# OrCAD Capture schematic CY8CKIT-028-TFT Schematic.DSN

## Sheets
1 01. Title Page: title: CY8CKIT-028-TFT TFT Display Shield; rev: 04; note: 630-60377-01
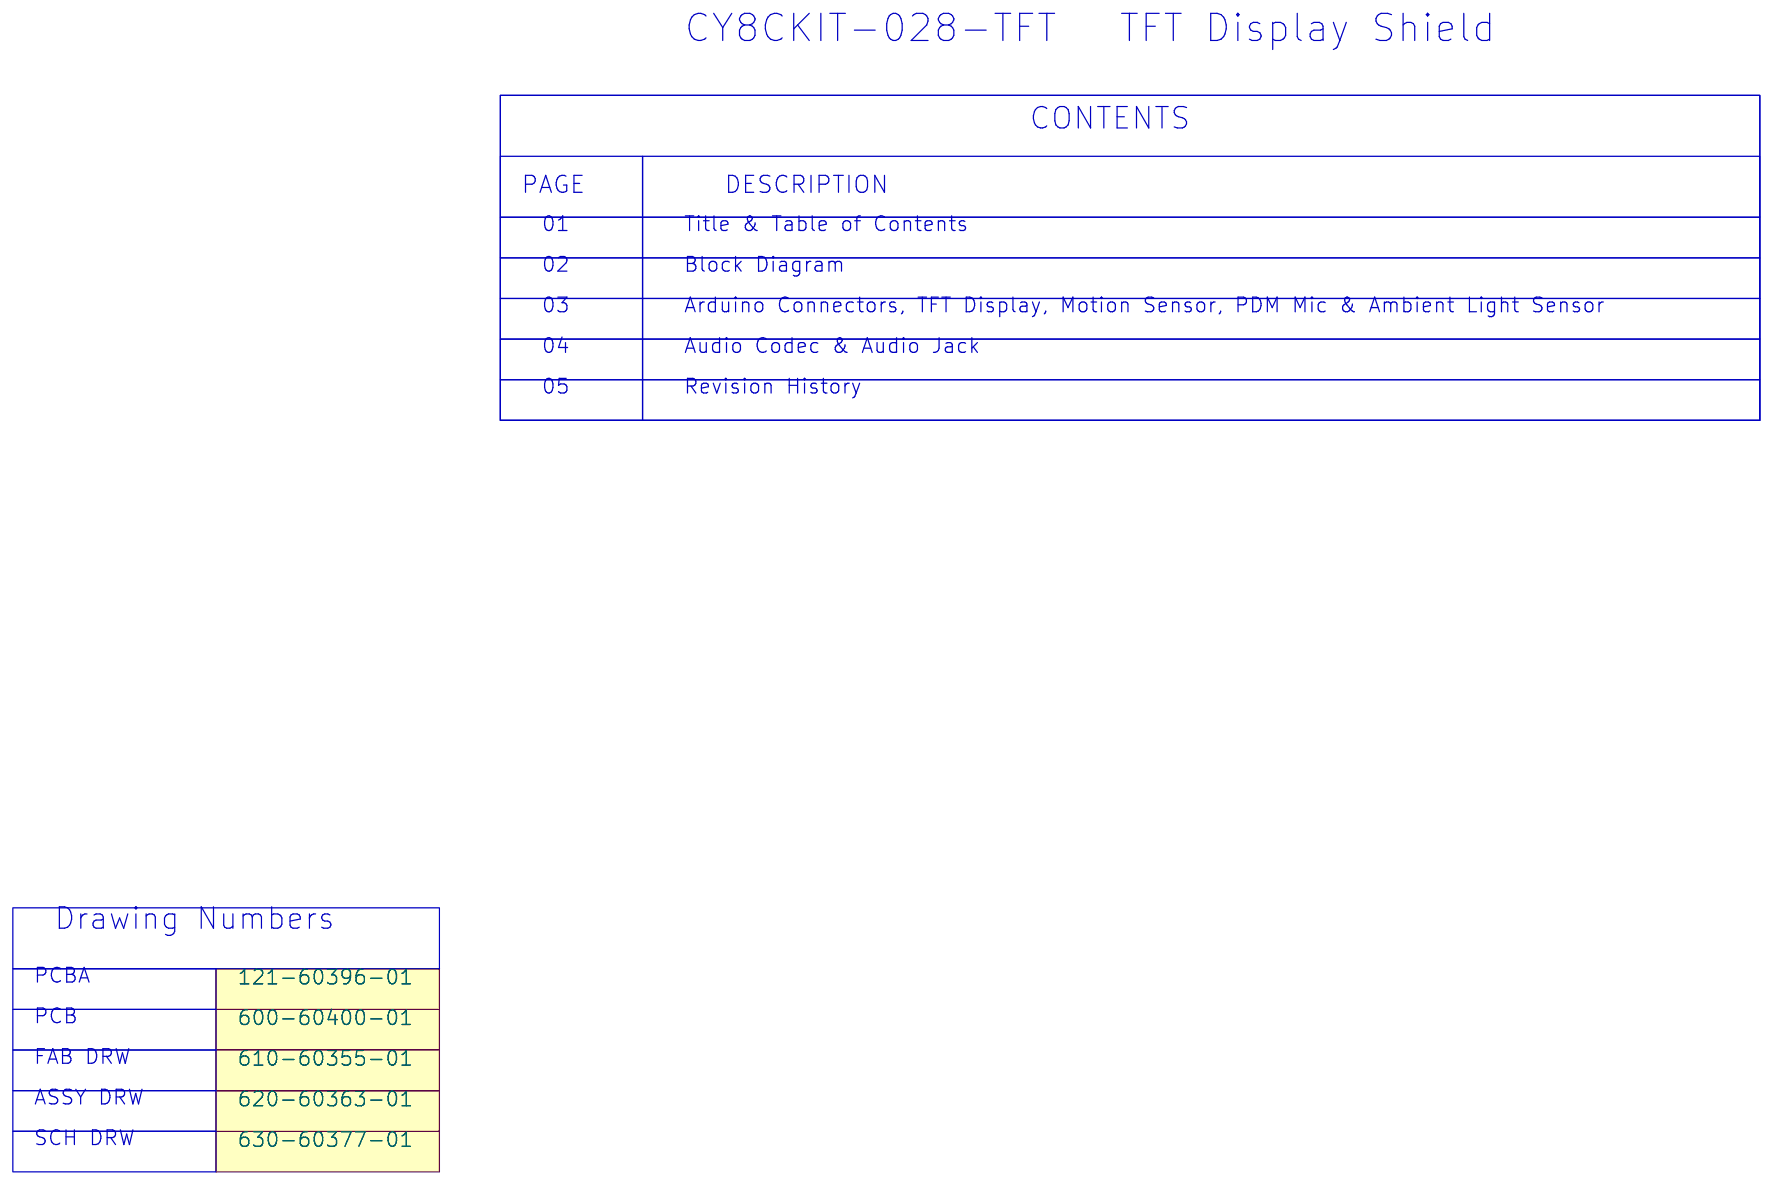
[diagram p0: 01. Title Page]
2 02. Block Diagram
3 03. Arduino,TFT, PDM, IMU & ALS: size A4
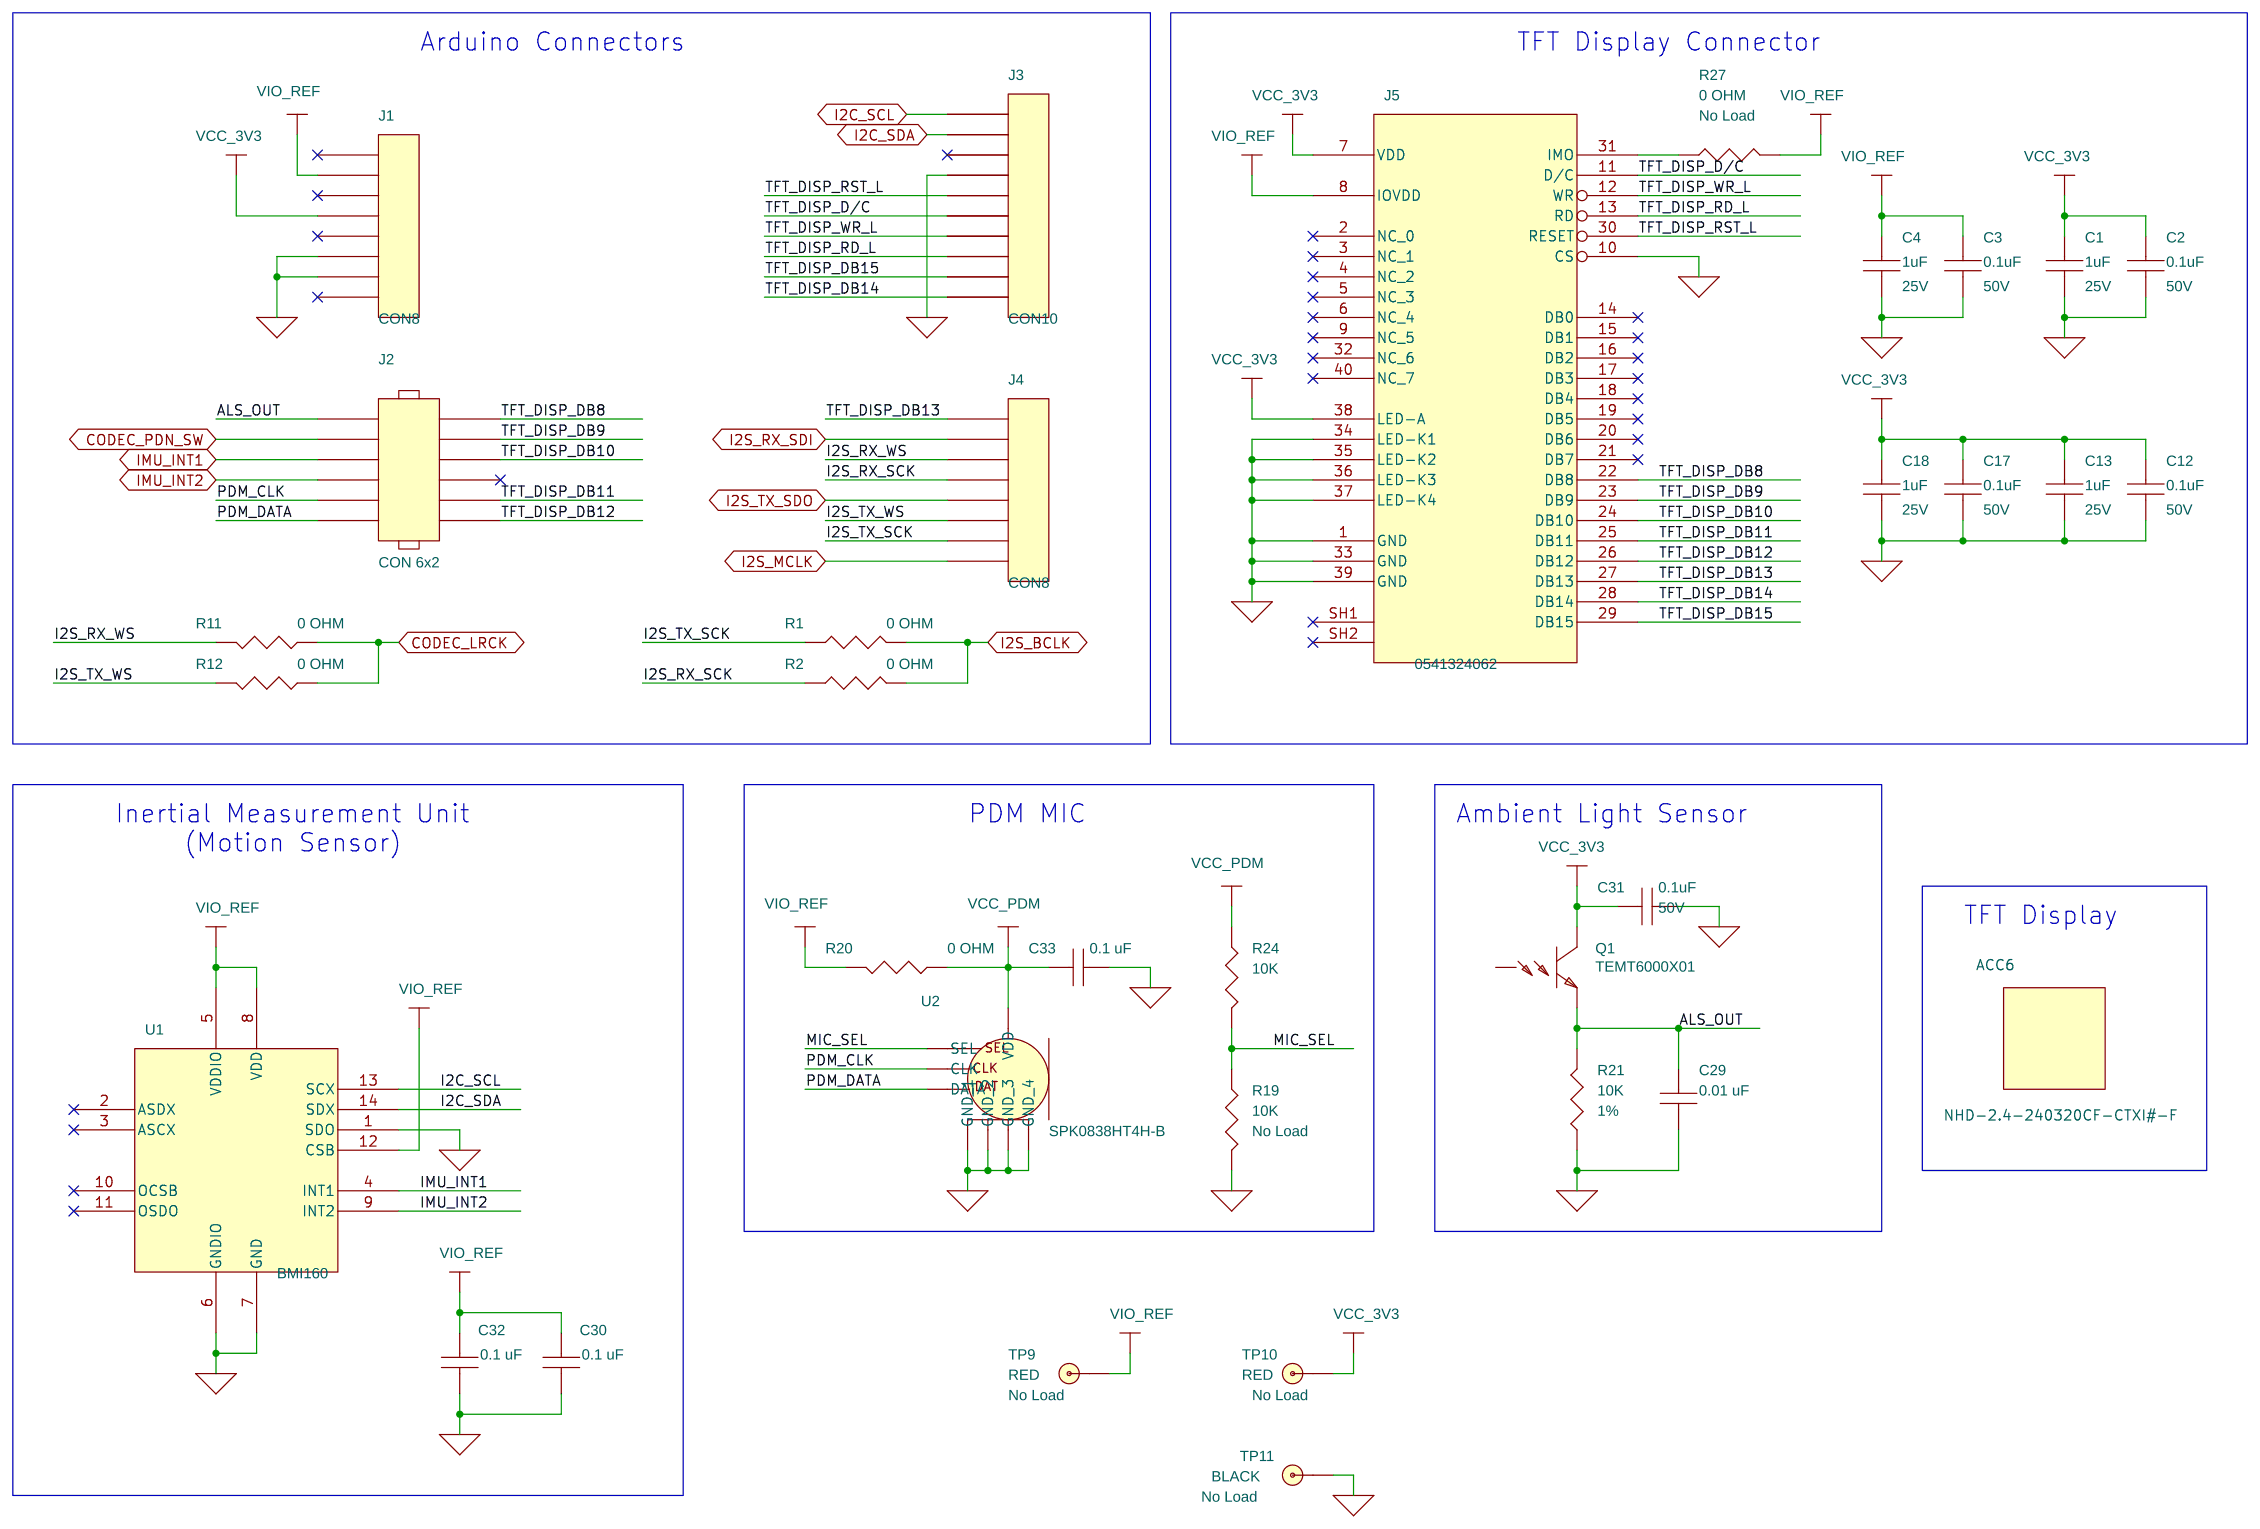
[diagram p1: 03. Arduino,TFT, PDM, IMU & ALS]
4 04. Audio Codec: size A4
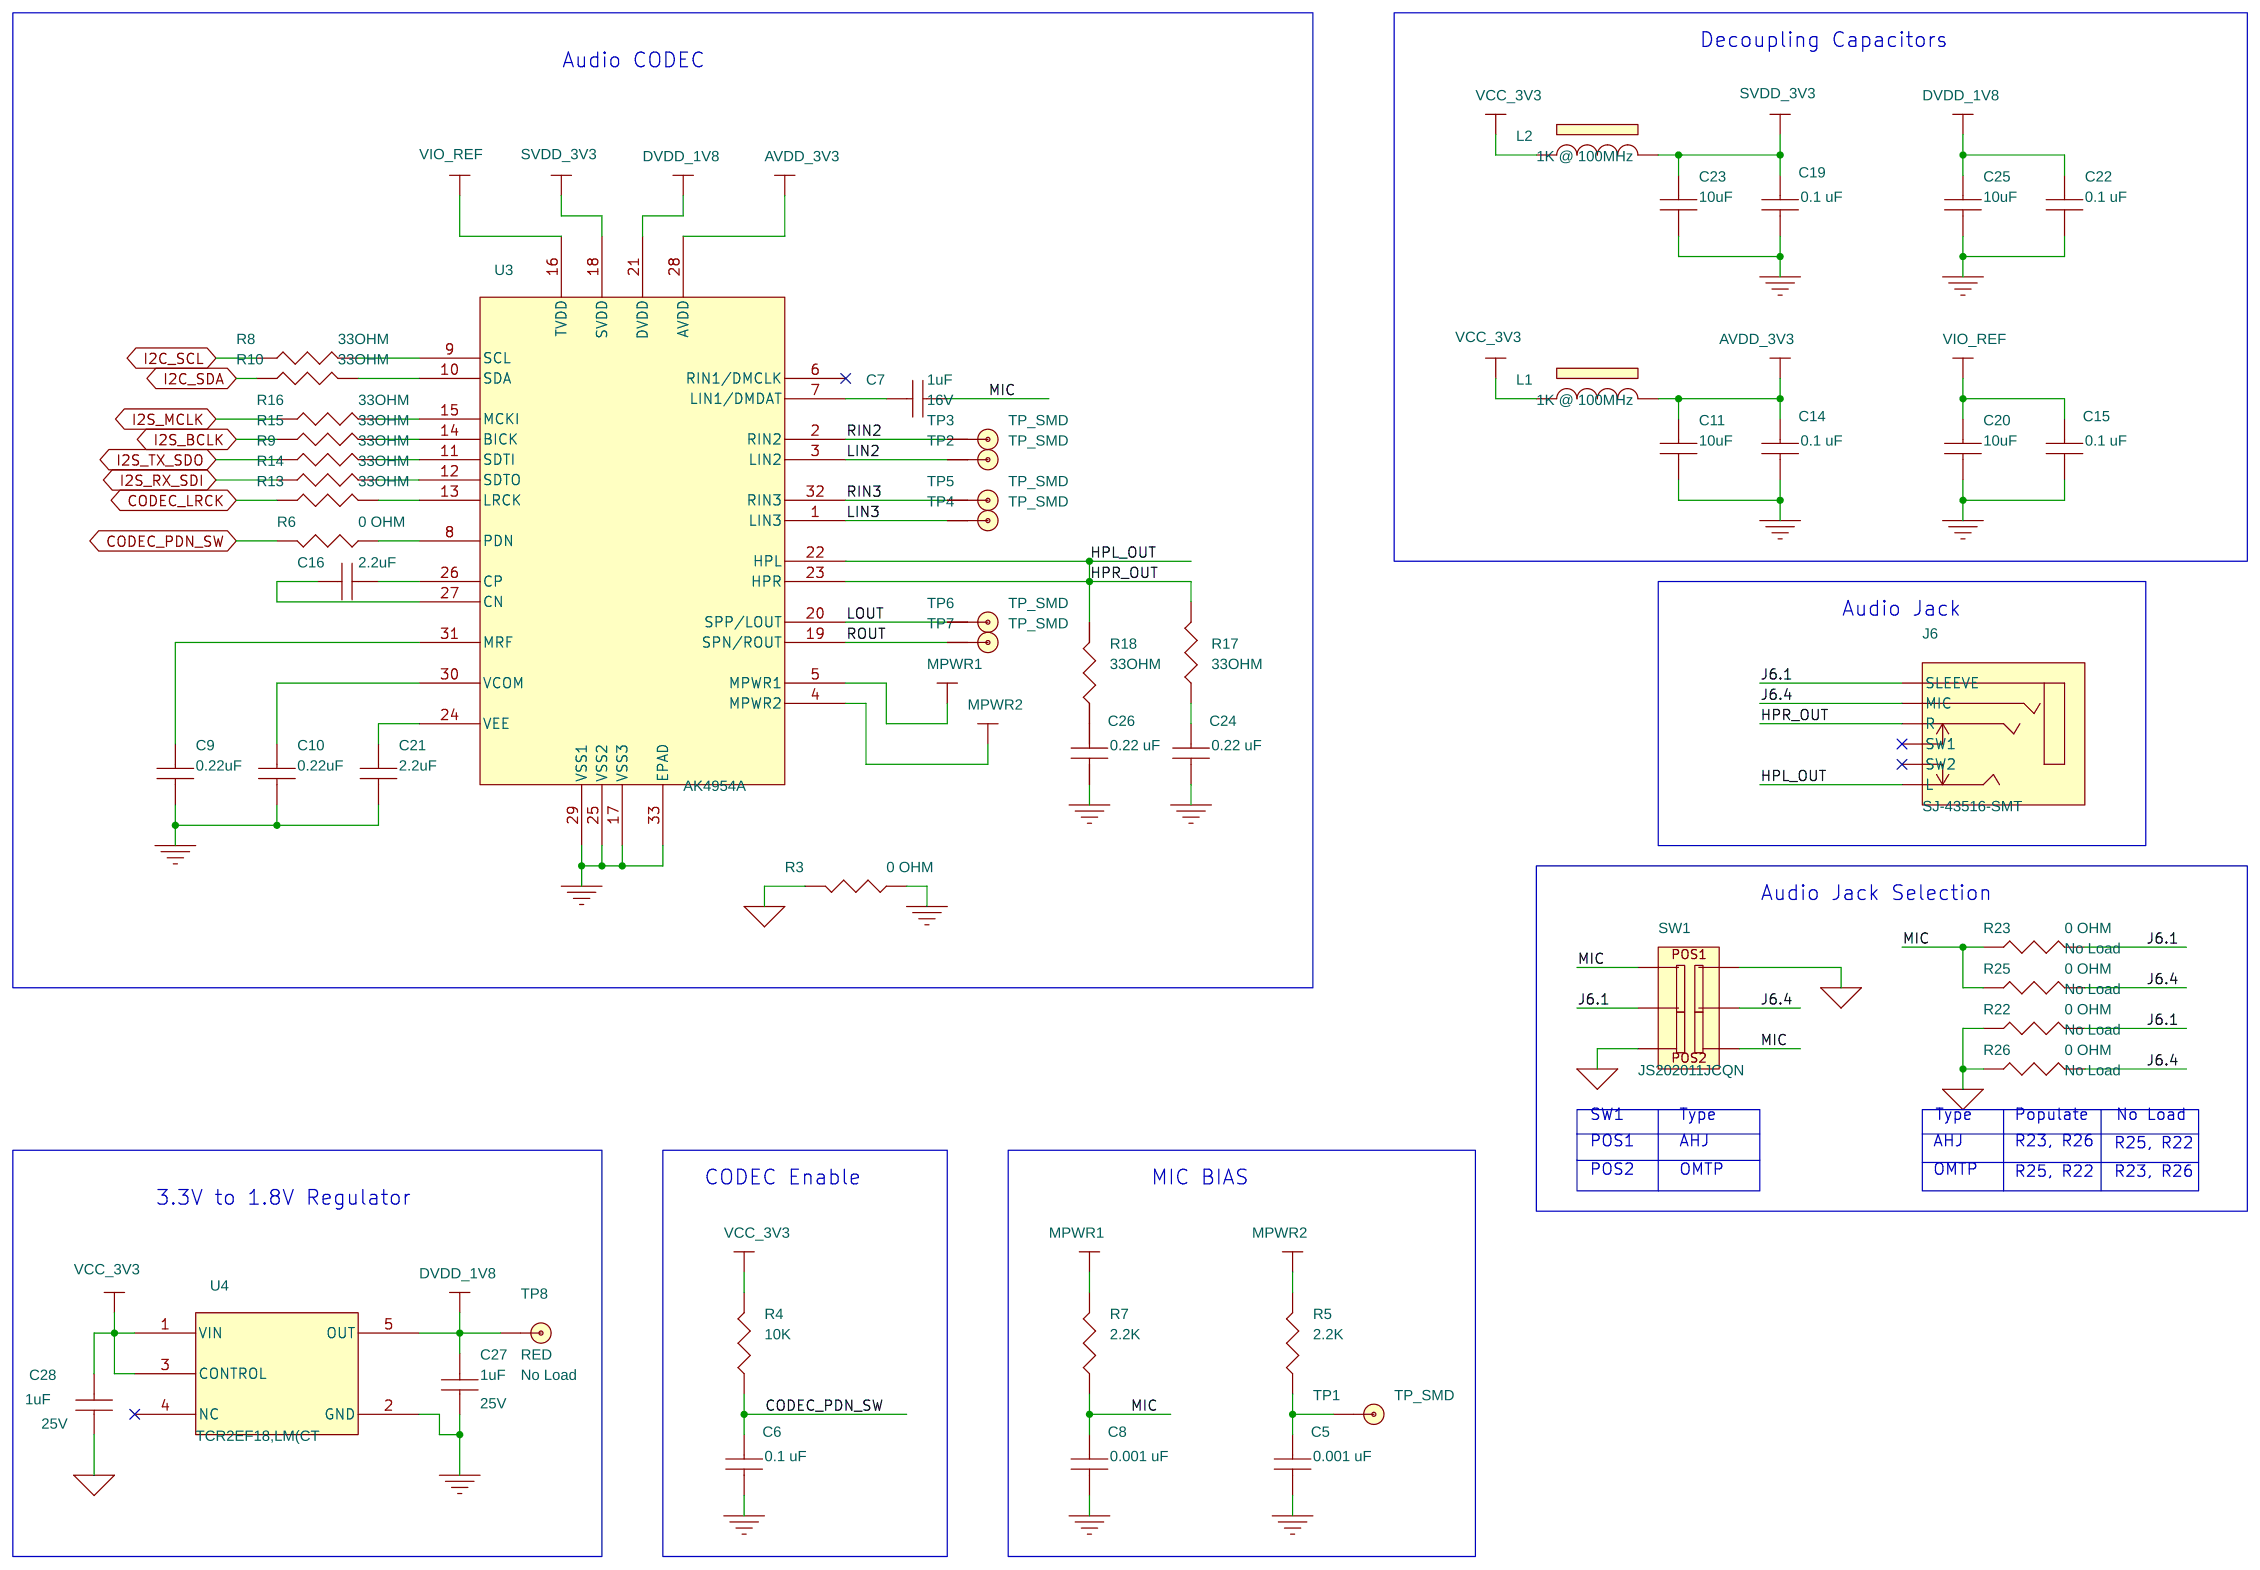
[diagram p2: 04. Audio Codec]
5 05. Revision History
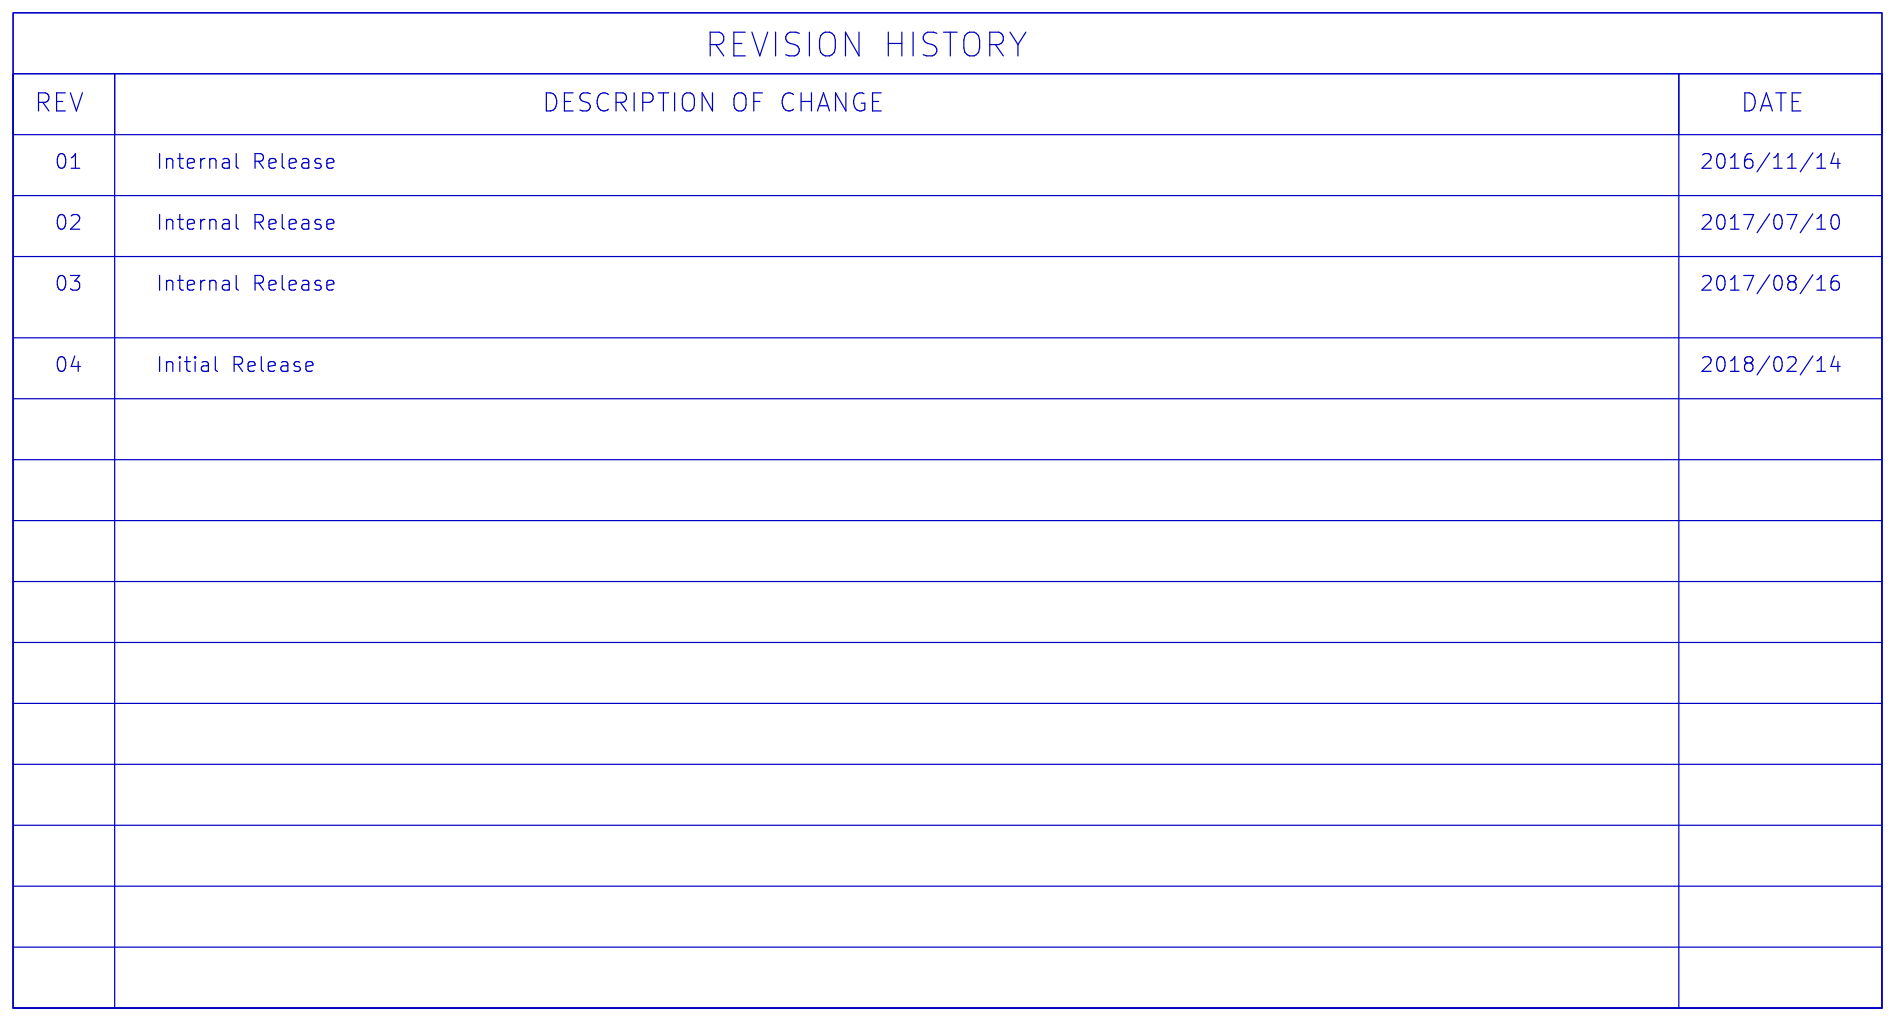
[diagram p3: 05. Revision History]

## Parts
sheet 01. Title Page
ACC1  121-60396-01  [TBD]
ACC2  600-60400-01  [TBD]
ACC3  610-60355-01  [TBD]
ACC4  620-60363-01  [TBD]
ACC5  630-60377-01  [TBD]
sheet 03. Arduino,TFT, PDM, IMU & ALS
ACC6  NHD-2.4-240320CF-CTXI#-F
C1  1uF  [CAPC1005X55M_D]
C2  0.1uF  [CAPC1005X55M_C]
C3  0.1uF  [CAPC1005X55M_C]
C4  1uF  [CAPC1005X55M_D]
C12  0.1uF  [CAPC1005X55M_C]
C13  1uF  [CAPC1005X55M_D]
C17  0.1uF  [CAPC1005X55M_C]
C18  1uF  [CAPC1005X55M_D]
C29  0.01 uF  [CAPC1005X55M_C]
C30  0.1 uF  [CAPC1005X55M_C]
C31  0.1uF  [CAPC1005X55M_C]
C32  0.1 uF  [CAPC1005X55M_C]
C33  0.1 uF  [CAPC1005X55M_C]
J1  CON8  [SULLINS_PBC08SAAN]
J2  CON 6x2  [SULLINS_PRPC006DAAN-RC_FLIP]
J3  CON10  [SULLINS_PBC10SAAN]
J4  CON8  [SULLINS_PBC08SAAN]
J5  0541324062  [molex_541324062_custom]
Q1  TEMT6000X01  [SENSOR_TEMT6000X01]
R1  0 OHM  [RESC1608X55M]
R2  0 OHM  [RESC1608X55M]
R11  0 OHM  [RESC1608X55M_A]
R12  0 OHM  [RESC1608X55M_A]
R19  10K  [RESC1005X40M_A]
R20  0 OHM  [RESC1608X55M_A]
R21  10K  [RESC1608X55M]
R24  10K  [RESC1005X40M_A]
R27  0 OHM  [RESC1608X55M]
TP9  RED  [KEYSTONE_5000]
TP10  RED  [KEYSTONE_5000]
TP11  BLACK  [KEYSTONE_5000]
U1  BMI160  [BOSCH_BMI160]
U2  SPK0838HT4H-B  [KNOWLES_SPK0838HT4H-B]
sheet 04. Audio Codec
C5  0.001 uF  [CAPC1608X90M]
C6  0.1 uF  [CAPC1005X55M_C]
C7  1uF  [CAPC1005X55M_D]
C8  0.001 uF  [CAPC1608X90M]
C9  0.22uF  [CAPC1608X90M]
C10  0.22uF  [CAPC1608X90M]
C11  10uF  [CAPC1608X90M]
C14  0.1 uF  [CAPC1005X55M_C]
C15  0.1 uF  [CAPC1005X55M_C]
C16  2.2uF  [CAPC1608X90M]
C19  0.1 uF  [CAPC1005X55M_C]
C20  10uF  [CAPC1608X90M]
C21  2.2uF  [CAPC1608X90M]
C22  0.1 uF  [CAPC1005X55M_C]
C23  10uF  [CAPC1608X90M]
C24  0.22 uF  [CAPC1608X90M]
C25  10uF  [CAPC1608X90M]
C26  0.22 uF  [CAPC1608X90M]
C27  1uF  [CAPC1005X55M_D]
C28  1uF  [CAPC1005X55M_D]
J6  SJ-43516-SMT  [CUI_SJ-43516-SMT-TR]
L1  1K @ 100MHz  [INDC2012X105M]
L2  1K @ 100MHz  [INDC2012X105M]
R3  0 OHM  [RESC1608X55M_A]
R4  10K  [RESC1005X40M]
R5  2.2K  [RESC1005X40M]
R6  0 OHM  [RESC1608X55M_A]
R7  2.2K  [RESC1005X40M]
R8  33OHM  [RESC1005X40M_B]
R9  33OHM  [RESC1005X40M_B]
R10  33OHM  [RESC1005X40M_B]
R13  33OHM  [RESC1005X40M_B]
R14  33OHM  [RESC1005X40M_B]
R15  33OHM  [RESC1005X40M_B]
R16  33OHM  [RESC1005X40M_B]
R17  33OHM  [RESC1005X40M_B]
R18  33OHM  [RESC1005X40M_B]
R22  0 OHM  [RESC1608X55M]
R23  0 OHM  [RESC1608X55M]
R25  0 OHM  [RESC1608X55M]
R26  0 OHM  [RESC1608X55M]
SW1  JS202011JCQN  [SW_JS202011JCQN]
TP1  TP_SMD  [TP102C]
TP2  TP_SMD  [TP102C]
TP3  TP_SMD  [TP102C]
TP4  TP_SMD  [TP102C]
TP5  TP_SMD  [TP102C]
TP6  TP_SMD  [TP102C]
TP7  TP_SMD  [TP102C]
TP8  RED  [KEYSTONE_5000]
U3  AK4954A  [QFN40P400X400X80-33N]
U4  TCR2EF18,LM(CT  [SOT95P275X140-5M]

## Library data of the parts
ACC1 = PCB_0: ASSY, PCBA, CY8CKIT-028-TFT TFT Display Shield; Dist_Part_Number: -NA-; Distributor: -NA-; Mfr_Name: Cypress Approved CM; Mfr_Part#: -NA-; Mfr_Part_Number: -NA-
ACC2 = PCB_0: PCB, BARE, CY8CKIT-028-TFT TFT Display Shield; Dist_Part_Number: -NA-; Distributor: -NA-; Mfr_Name: Cypress Approved CM; Mfr_Part#: -NA-; Mfr_Part_Number: -NA-
ACC3 = PCB_0: DRW, FABRICATION DRAWING, CY8CKIT-028-TFT TFT Display Shield; Dist_Part_Number: -NA-; Distributor: -NA-; Mfr_Name: Cypress Approved CM; Mfr_Part#: -NA-; Mfr_Part_Number: -NA-
ACC4 = PCB_0: DRW, ASSEMBLY DRAWING, CY8CKIT-028-TFT TFT Display Shield; Dist_Part_Number: -NA-; Distributor: -NA-; Mfr_Name: Cypress Approved CM; Mfr_Part#: -NA-; Mfr_Part_Number: -NA-
ACC5 = PCB_0: DRW, SCHEMATIC DRAWING, CY8CKIT-028-TFT TFT Display Shield; Dist_Part_Number: -NA-; Distributor: -NA-; Mfr_Name: Cypress Approved CM; Mfr_Part#: -NA-; Mfr_Part_Number: -NA-
ACC6 = E1260CS021: 2.7" TFT Display; Mfr_Name: Newhaven Display Intl; ROHS: YES
C1 C4 C13 C18 C27 C28 = CAPACITOR_NON-POL: CAP, CER, 1UF, 10%, 25V, X5R, 0402; Mfr_Name: Murata Electronics; Mfr_Part#: GRM155R61E105KA12D; Tolerance: 10%; VOLTAGE: 25V
C2 C3 C12 C17 C31 = CAPACITOR_NON-POL: CAP, CER, 0.1UF, 10%, X5R, 50V, 0402; Cy_Part#: 510-60330-01; Mfr_Name: Taiyo Yuden; Mfr_Part#: UMK105BJ104KV-F; Tolerance: 10%; VOLTAGE: 50V
C29 = CAPACITOR_NON-POL: CAP CER 10000PF 50V X7R 0402; Mfr_Name: Murata Electronics; Mfr_Part#: GRM155R71H103KA88D; Mfr_Part_Number: GRM155R71H103KA88D
C6 C14 C15 C19 C22 C30 C32 = CAPACITOR_NON-POL: CAP, 0.1UF, Y5V, 16V, 0402; Mfr_Name: Samsung Electro-Mechanics America, Inc.; Mfr_Part#: CL05F104ZO5NNNC; Mfr_Part_Number: CL05F104ZO5NNNC
C33 = CAPACITOR_NON-POL: CAP, CER, 0.1UF, 10%, X5R, 50V, 0402; Cy_part#: 510-60330-01; Mfr_Name: Taiyo Yuden; Mfr_Part#: UMK105BJ104KV-F; VOLTAGE: 50V
J1 J4 = CONN_PCB_8: HEADER, MALE, .100", SNGL, STR, 8POS, SMD; HARD_LOCATION: YES; Mfr_Name: Sullins Connector Solutions; Mfr_Part#: PBC08SAAN
J2 = CONN_PLUG_6x2: CONN HEADER .100" DUAL STR 12POS; HARD_LOCATION: YES; Mfr_Name: Sullins Connector Solutions; Mfr_Part#: PRPC006DAAN-RC
J3 = CONN_PCB_10: HEADER, MALE, .100", SNGL, STR, 10POS; Cy_part#: 710-60055-01; HARD_LOCATION: YES; Mfr_Name: Sullins Connector Solutions; Mfr_Part#: PBC10SAAN
J5 = E1260CS021_CONN_11: CONN FPC BOTTOM 40POS 0.50MM R/A; Dist_Part_Number: A100226CT-ND; Distributor: Digikey; Mfr_Name: TE Connectivity AMP Connectors; Mfr_Part#: 4-1734592-0; Mfr_Part_Number: 4-1734592-0; ROHS: YES; Sub_Allowed: ASK; UL: YES
Q1 = PHOTO_NPN_5: AMBIENT LIGHT SENSOR 1206 SMD; Mfr_Name: Vishay Semiconductor
R1 = RESISTOR: RES SMD 0.0OHM JUMPER 1/10W 0603; Cy_part#: 500-60108-01; Mfr_Name: Rohm Semiconductor; Mfr_Part#: MCR03EZPJ000; Mfr_Part_Number: MCR03EZPJ000
R2 = RESISTOR: RES SMD 0.0OHM JUMPER 1/10W 0603; Asm_Instruction: <Asm_Instruction>; Cy_part#: 500-60108-01; Mfr_Name: Rohm Semiconductor; Mfr_Part#: MCR03EZPJ000; Mfr_Part_Number: MCR03EZPJ000
R3 R6 R11 R12 R20 = RESISTOR: RES SMD 0.0OHM JUMPER 1/10W 0603; Cy_part#: 500-60108-01; Mfr_Name: Rohm Semiconductor; Mfr_Part#: MCR03EZPJ000
R19 = RESISTOR: RES, 10K OHM, 1/16W, 5%, 0402, SMD; Asm_Instruction: No Load; Cy_part#: 500-60044-01; Mfr_Name: Yageo; Mfr_Part#: RC0402JR-0710KL; Mfr_Part_Number: RC0402JR-0710KL; Tolerance: 5%
R21 = RESISTOR: RES SMD 10K OHM 1% 1/10W 0603; Mfr_Name: Yageo; Mfr_Part#: RC0603FR-0710KL; Tolerance: 1%
R24 = RESISTOR: RES, 10K OHM, 1/16W, 5%, 0402, SMD; Cy_part#: 500-60044-01; Mfr_Name: Yageo; Mfr_Part#: RC0402JR-0710KL; Mfr_Part_Number: RC0402JR-0710KL; Tolerance: 5%
R22 R23 R25-R27 = RESISTOR: RES SMD 0.0OHM JUMPER 1/10W 0603; Asm_Instruction: No Load; Cy_part#: 500-60108-01; Mfr_Name: Rohm Semiconductor; Mfr_Part#: MCR03EZPJ000; Mfr_Part_Number: MCR03EZPJ000
TP9 TP10 = TEST_POINT: CONN, TEST POINT, RED, TH; Asm_Instruction: No Load; Mfr_Name: Keystone Electronics; Mfr_Part#: 5000
TP11 = TEST_POINT: TEST POINT PC MINI .040"D BLACK; Asm_Instruction: No Load; CLASS: DISCRETE; Cy_Part_Number: 711-60002-01; Cy_part#: 711-60002-01; Dist_Part_Number: 36-5001-ND; Distributor: Digikey; Mfr_Name: Keystone Electronics; Mfr_Part#: 5001; Mfr_Part_Number: 5001; ROHS: YES; Sub_Allowed: ASK; UL: YES
U1 = BMI160: IMU ACCEL/GYRO I2C/SPI 14LGA; Mfr_Name: Bosch Sensortec
U2 = SPK0838HT4H-B: MIC MEMS DIGITAL; Mfr_Name: Knowles
C5 C8 = CAPACITOR_NON-POL: CAP CER 0.001UF 50V X7R 0603; Mfr_Name: Samsung Electro-Mechanics America, Inc.; Mfr_Part#: CL10B102KB85PNL; Mfr_Part_Number: CL10B102KB85PNL; VOLTAGE: 50V
C7 = CAPACITOR_NON-POL: CAP CER 1UF 16V X5R 0402; Cy_part#: 510-60391-01; Dist_Part_Number: 490-10694-1-ND; Distributor: Digikey; Mfr_Name: Murata; Mfr_Part#: GRM155R61C105KA12D; Mfr_Part_Number: GRM155R61C105KA12D; ROHS: YES; Sub_Allowed: ASK; UL: YES; VOLTAGE: 16V
C9 C10 C24 C26 = CAPACITOR_NON-POL: CAP, CER, 0.22UF, 16V, X7R, 0603; Mfr_Name: TDK Corporation; Mfr_Part#: C1608X7R1C224K080AC; Mfr_Part_Number: C1608X7R1C224K080AC; VOLTAGE: 16V
C11 C20 C23 C25 = CAPACITOR_NON-POL: CAP CER 10UF 6.3V 10% JB 0603; Mfr_Name: TDK Corporation; Mfr_Part#: C1608JB0J106K080AB; Mfr_Part_Number: C1608JB0J106K080AB; VOLTAGE: 25V
C16 C21 = CAPACITOR_NON-POL: CAP CER 2.2UF 16V X5R 0603; Mfr_Name: Murata Electronics; Mfr_Part#: GRM188R61C225KE15D; Mfr_Part_Number: GRM188R61C225KE15D; VOLTAGE: 16V
J6 = PJ-3755B-PA6T-TR_3: 3.5mm SMD EARPHONE JACK,(TSH-3756); Mfr_Name: CUI; Package: SMD; Terasic_Prt: MJJ-3043-SHU; Type: Connector
L1 L2 = INDUCTOR_FERRITE: FERRITE BEAD 1 KOHM 0805; CLASS: DISCRETE; Mfr_Name: Murata Electronics; Mfr_Part#: BLM21AG102SN1D; PART_TYPE: FERRITE; ROHS: YES
R4 = RESISTOR: RES SMD 10K OHM 5% 1/16W 0402; CLASS: DISCRETE; Mfr_Name: Yageo; Mfr_Part#: RC0402JR-0710KL; Mfr_Part_Number: RC0402JR-0710KL
R5 R7 = RESISTOR: RES SMD 2.2K OHM 5% 1/16W 0402; CLASS: DISCRETE; Mfr_Name: Yageo; Mfr_Part#: RC0402JR-072K2L; Mfr_Part_Number: RC0402JR-072K2L
R8-R10 R13-R18 = RESISTOR: RES SMD 33 OHM 1% 1/16W 0402; Cy_part#: TBD; Mfr_Name: 'YAGEO; Mfr_Part#: RC0402FR-0733RL; Mfr_Part_Number: RC0402FR-0733RL; Tolerance: 1%
SW1 = SW_DPDT_JS202011CQN_1: SWITCH SLIDE DPDT 300MA 6V; Mfr_Name: C&K Components; Sub_Asm: Power In
TP1-TP7 = TEST_POINT: TESTPOINT, SMD, 40MILS, ROUND; Asm_Instruction: No Load; Mfr_Name: -NA-; Mfr_Part#: -NA-
TP8 = TEST_POINT: CONN, TEST POINT, RED, TH; Asm_Instruction: No Load; CLASS: DISCRETE; Mfr_Name: Keystone Electronics; Mfr_Part#: 5000
U3 = AK4954A_0: IC STEREO CODEC 32BIT 32QFN; Mfr_Name: AKM Semiconductor Inc.; Mfr_Part#: AK4954AEN; Mfr_Part_Number: AK4954AEN
U4 = AP22802_3: IC REG LDO 1.8V 0.2A SMV; Mfr_Name: Toshiba Semiconductor

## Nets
AGND: C5.2 C6.2 C8.2 C9.2 C10.2 C11.2 C14.2 C15.2 C19.2 C20.2 C21.2 C22.2 C23.2 C24.2 C25.2 C26.2 C27.1 R3.2 U3.17(VSS3) U3.25(VSS2) U3.29(VSS1) U3.33(EPAD) U4.2(GND)
AVDD_3V3: C11.1 C14.1 L1.2 U3.28(AVDD)
DVDD_1V8: C22.1 C25.1 C27.2 TP8.1 U3.21(DVDD) U4.5(OUT)
GND_SIGNAL: C1.2 C2.2 C3.2 C4.2 C12.2 C13.2 C17.2 C18.2 C28.1 C29.2 C30.2 C31.2 C32.2 C33.2 J1.2 J1.3 J3.7 J5.1(GND) J5.10(CS) J5.33(GND) J5.34(LED-K1) J5.35(LED-K2) J5.36(LED-K3) J5.37(LED-K4) J5.39(GND) R3.1 R19.2 R21.1 R22.1 R26.1 SW1.3 SW1.5 TP11.1 U1.1(SDO) U1.6(GNDIO) U1.7(GND) U2.5(GND_1) U2.6(GND_2) U2.7(GND_3) U2.8(GND_4)
SVDD_3V3: C19.1 C23.1 L2.2 U3.18(SVDD)
VCC_3V3: C1.1 C2.1 C12.1 C13.1 C17.1 C18.1 C28.2 C31.1 J1.5 J5.7(VDD) J5.38(LED-A) L1.1 L2.1 Q1.2(COLLECTOR) R4.2 TP10.1 U4.1(VIN) U4.3(CONTROL)
VCC_PDM: C33.1 R20.1 R24.1 U2.1(VDD)
ALS_OUT: C29.1 J2.1 Q1.1(EMITTER) R21.2
CODEC_LRCK: R11.1 R12.1 R13.1
CODEC_PDN_SW: C6.1 J2.3 R4.1 R6.2
HPL_OUT: J6.2(L) R18.2 U3.22(HPL)
HPR_OUT: J6.3(R) R17.2 U3.23(HPR)
I2C_SCL: J3.10 R8.1 U1.13(SCX)
I2C_SDA: J3.9 R10.1 U1.14(SDX)
I2S_BCLK: R1.1 R2.1 R15.1
I2S_MCLK: J4.1 R16.1
I2S_RX_SCK: J4.5 R2.2
I2S_RX_SDI: J4.7 R14.1
I2S_RX_WS: J4.6 R11.2
I2S_TX_SCK: J4.2 R1.2
I2S_TX_SDO: J4.4 R9.1
I2S_TX_WS: J4.3 R12.2
IMU_INT1: J2.5 U1.4(INT1)
IMU_INT2: J2.7 U1.9(INT2)
J6.1: J6.1(SLEEVE) R22.2 R23.2 SW1.2
J6.4: J6.4(MIC) R25.2 R26.2 SW1.6
LIN2: TP2.1 U3.3(LIN2)
LIN3: TP4.1 U3.1(LIN3)
LOUT: TP6.1 U3.20(SPP/LOUT)
MIC: C7.1 C8.1 R7.1 R23.1 R25.1 SW1.1 SW1.7
MIC_SEL: R19.1 R24.2 U2.2(SEL)
MPWR1: R7.2 U3.5(MPWR1)
MPWR2: R5.2 U3.4(MPWR2)
NC: Q1.3(NC)
PDM_CLK: J2.9 U2.3(CLK)
PDM_DATA: J2.11 U2.4(DATA)
RIN2: TP3.1 U3.2(RIN2)
RIN3: TP5.1 U3.32(RIN3)
ROUT: TP7.1 U3.19(SPN/ROUT)
TFT_DISP_D/C: J3.5 J5.11(D/C)
TFT_DISP_DB8: J2.2 J5.22(DB8)
TFT_DISP_DB9: J2.4 J5.23(DB9)
TFT_DISP_DB10: J2.6 J5.24(DB10)
TFT_DISP_DB11: J2.10 J5.25(DB11)
TFT_DISP_DB12: J2.12 J5.26(DB12)
TFT_DISP_DB13: J4.8 J5.27(DB13)
TFT_DISP_DB14: J3.1 J5.28(DB14)
TFT_DISP_DB15: J3.2 J5.29(DB15)
TFT_DISP_RD_L: J3.3 J5.13(RD)
TFT_DISP_RST_L: J3.6 J5.30(RESET)
TFT_DISP_WR_L: J3.4 J5.12(WR)
VIO_REF: C3.1 C4.1 C15.1 C20.1 C30.1 C32.1 J1.7 J5.8(IOVDD) R20.2 R27.2 TP9.1 U1.5(VDDIO) U1.8(VDD) U1.12(CSB) U3.16(TVDD)
N17232509: J5.31(IMO) R27.1
N17262592: R8.2 U3.9(SCL)
N17262616: R10.2 U3.10(SDA)
N17313413: C7.2 U3.7(LIN1/DMDAT)
N17337588: R6.1 U3.8(PDN)
N17337626: R16.2 U3.15(MCKI)
N17337628: R15.2 U3.14(BICK)
N17337654: R9.2 U3.11(SDTI)
N17337656: R14.2 U3.12(SDTO)
N17337674: R13.2 U3.13(LRCK)
N17337833: C16.2 U3.26(CP)
N17337835: C16.1 U3.27(CN)
N17337935: C10.1 U3.30(VCOM)
N17337954: C9.1 U3.31(MRF)
N17338534: C21.1 U3.24(VEE)
N17339065: C24.1 R17.1
N17348097: C5.1 R5.1 TP1.1
N17360634: C26.1 R18.1

Not connected (* = marked no-connect by the designer): J1 1* 4* 6* 8*; J2 8*; J3 8*; J5 2(NC_0)* 3(NC_1)* 4(NC_2)* 5(NC_3)* 6(NC_4)* 9(NC_5)* 14(DB0)* 15(DB1)* 16(DB2)* 17(DB3)* 18(DB4)* 19(DB5)* 20(DB6)* 21(DB7)* 32(NC_6)* 40(NC_7)* SH1* SH2*; J6 5(SW2)* 6(SW1)*; U1 2(ASDX)* 3(ASCX)* 10(OCSB)* 11(OSDO)*; U3 6(RIN1/DMCLK)*; U4 4(NC)*

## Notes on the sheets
sheet 1
- CY8CKIT-028-TFT   TFT Display Shield
- CONTENTS
- PAGE
- DESCRIPTION
- 01
- Title & Table of Contents
- 02
- Block Diagram
- 03
- Arduino Connectors, TFT Display, Motion Sensor, PDM Mic & Ambient Light Sensor
- 04
- Audio Codec & Audio Jack
- 05
- Revision History
- Drawing Numbers
- PCBA
- PCB
- FAB DRW
- ASSY DRW
- SCH DRW
sheet 3
- Arduino Connectors
- TFT Display Connector
- Inertial Measurement Unit
       (Motion Sensor)
- PDM MIC
- Ambient Light Sensor
- TFT Display
sheet 4
- Decoupling Capacitors
- Audio CODEC
- Audio Jack
- Audio Jack Selection
- SW1
- Type
- Type
- Populate
- No Load
- POS1
- AHJ
- AHJ
- R23, R26
- R25, R22
- CODEC Enable
- MIC BIAS
- POS2
- OMTP
- OMTP
- R25, R22
- R23, R26
- 3.3V to 1.8V Regulator
sheet 5
- REVISION HISTORY
- REV
- DESCRIPTION OF CHANGE
- DATE
- 01
- Internal Release
- 2016/11/14
- 02
- Internal Release
- 2017/07/10
- 03
- Internal Release
- 2017/08/16
- 04
- Initial Release
- 2018/02/14
